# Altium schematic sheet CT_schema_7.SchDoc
size 278 x 170 mm
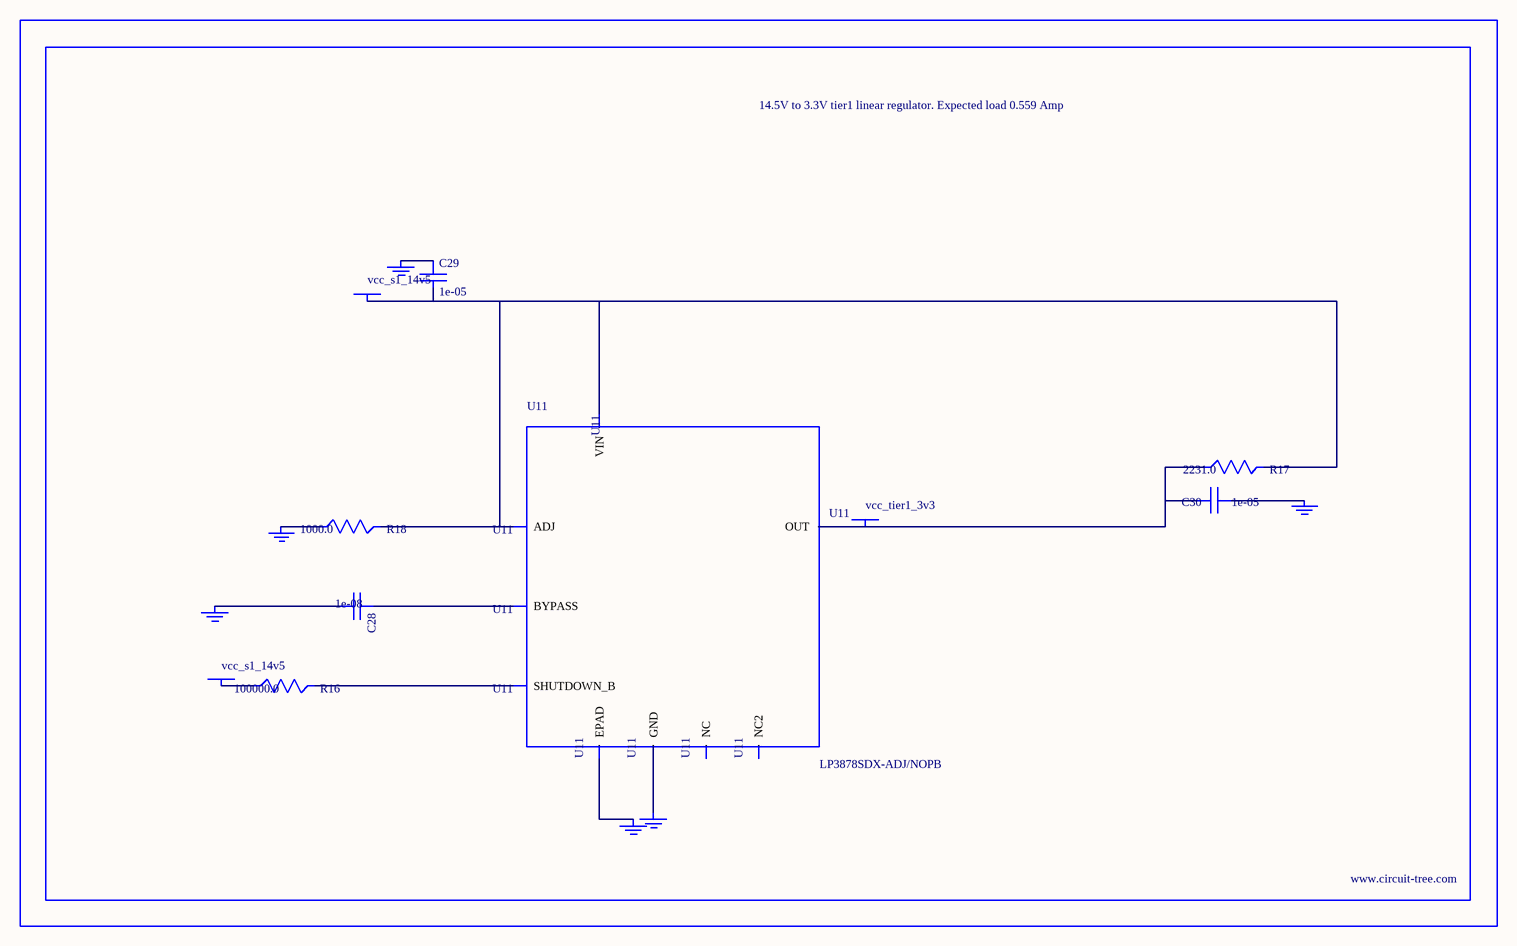
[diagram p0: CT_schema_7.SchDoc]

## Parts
BORDER6  (no value)
C28  1e-08  [C0402]
C29  1e-05  [C1210]
C30  1e-05  [C1210]
GND_INSTANCE_6_0  (no value)
GND_INSTANCE_6_1  (no value)
GND_INSTANCE_6_2  (no value)
GND_INSTANCE_6_3  (no value)
GND_INSTANCE_6_4  (no value)
GND_INSTANCE_6_5  (no value)
POWER_INSTANCE_6_0  vcc_s1_14v5
POWER_INSTANCE_6_1  vcc_s1_14v5
POWER_INSTANCE_6_2  vcc_tier1_3v3
R16  100000.0  [R0603]
R17  2231.0  [R0603]
R18  1000.0  [R0603]
U11  LP3878SDX-ADJ/NOPB  [WSON-8]

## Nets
NetC28_1: C28.1 U11.1(BYPASS)
NetC28_2: C28.2 GND_INSTANCE_6_0.0(GND)
NetC29_1: C29.1 GND_INSTANCE_6_1.0(GND)
NetC29_2: C29.2 POWER_INSTANCE_6_0.0(PWR) R17.2 R18.2 U11.4(VIN) U11.6(ADJ)
NetC30_1: C30.1 GND_INSTANCE_6_2.0(GND)
NetC30_2: C30.2 POWER_INSTANCE_6_2.0(PWR) R17.1 U11.5(OUT)
NetGND_INSTANCE_6_3_0: GND_INSTANCE_6_3.0(GND) R18.1
NetGND_INSTANCE_6_4_0: GND_INSTANCE_6_4.0(GND) U11.PAD(EPAD)
NetGND_INSTANCE_6_5_0: GND_INSTANCE_6_5.0(GND) U11.3(GND)
NetPOWER_INSTANCE_6_1_0: POWER_INSTANCE_6_1.0(PWR) R16.1
NetR16_2: R16.2 U11.8(SHUTDOWN_B)

Not connected (* = marked no-connect by the designer): U11 2(NC) 7(NC2)

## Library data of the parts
BORDER6 = BORDER_PAGE6
C28 = C0402C103K3RAC
C29 = C1210C106K5PACTU
C30 = GRM32DR61E106MA12L
GND_INSTANCE_6_0-GND_INSTANCE_6_5 = GND
POWER_INSTANCE_6_0-POWER_INSTANCE_6_2 = PWR
R16 = RC0603JR-07100KL
R17 = R17
R18 = RC0603JR-071KL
